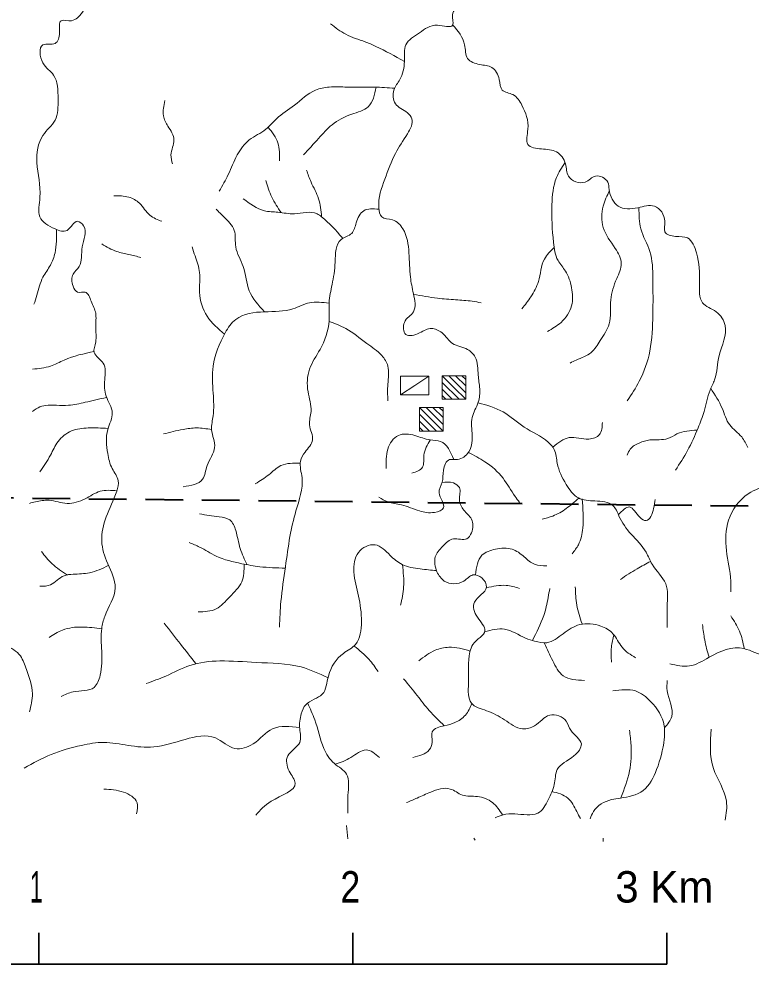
# Model space of a CAD drawing. Extents: x 788888 to 797112, y 8503144 to 8514989.
# Drawn here: x 791981 to 794313, y 8506322 to 8509330 of the extents above; entities that cross this region are included whole.
import ezdxf
from ezdxf.enums import TextEntityAlignment as Align

# ---------------------------------------------------------------- set-up
doc = ezdxf.new("R2010")
doc.units = 0
doc.header["$LTSCALE"] = 40
doc.linetypes.add('MEDIUM_DASHED', pattern=[4.5, 3, -1.5])
for name, color, linetype, lineweight in [('1', 7, 'Continuous', 13), ('15', 7, 'Continuous', 13), ('3', 7, 'Continuous', 13), ('60', 7, 'Continuous', 35), ('63', 7, 'MEDIUM_DASHED', 40)]:
    doc.layers.add(name, color=color, linetype=linetype, lineweight=lineweight)

msp = doc.modelspace()

# ---------------------------------------------------------------- linework, layer by layer
at = {"layer": '1'}
for p, q in [((793329.39, 8508194.65), (793367.39, 8508156.65)), ((793350.39, 8508194.65), (793404.39, 8508140.65)), ((793372.39, 8508194.65), (793404.39, 8508162.65)), ((793392.39, 8508194.65), (793404.39, 8508182.65)), ((793329.39, 8508173.65), (793383.39, 8508119.65)), ((793329.39, 8508151.65), (793361.39, 8508119.65)), ((793404.39, 8508119.65), (793367.39, 8508156.65)), ((793329.39, 8508131.65), (793341.39, 8508119.65)), ((793257.23, 8508093.43), (793295.23, 8508055.43)), ((793278.23, 8508093.43), (793332.23, 8508039.43)), ((793300.23, 8508093.43), (793332.23, 8508061.43)), ((793320.23, 8508093.43), (793332.23, 8508081.43)), ((793257.23, 8508072.43), (793311.23, 8508018.43)), ((793332.23, 8508018.43), (793295.23, 8508055.43)), ((793257.23, 8508050.43), (793289.23, 8508018.43)), ((793257.23, 8508030.43), (793269.23, 8508018.43))]:
    msp.add_line(p, q, dxfattribs=at)
for points in [[(793329.39, 8508194.65), (793329.39, 8508119.65), (793404.39, 8508119.65), (793404.39, 8508194.65)], [(793257.23, 8508093.43), (793257.23, 8508018.43), (793332.23, 8508018.43), (793332.23, 8508093.43)]]:
    msp.add_lwpolyline(points, close=True, dxfattribs=at)
at = {"layer": '15'}
for p, q in [((793025.16, 8506763.82), (793028.59, 8506721.2)), ((793434.68, 8506716.72), (793430.42, 8506723.11)), ((793841.86, 8506722.63), (793842.05, 8506712.23))]:
    msp.add_line(p, q, dxfattribs=at)
for points in [[(793382.88, 8509858.32), (793362.73, 8509818.94), (793367.53, 8509790.14), (793396.31, 8509766.15), (793410.69, 8509732.55), (793415.49, 8509684.55), (793449.06, 8509607.75), (793449.06, 8509545.35), (793420.29, 8509502.15), (793401.1, 8509473.35), (793401.1, 8509420.55), (793386.71, 8509377.36), (793362.73, 8509343.76), (793362.73, 8509310.16), (793314.77, 8509310.16), (793257.22, 8509286.16), (793214.05, 8509247.76), (793209.26, 8509194.96), (793194.87, 8509137.36), (793175.68, 8509103.76), (793180.48, 8509060.57), (793218.85, 8509031.77), (793233.24, 8509012.57), (793218.85, 8508964.57), (793180.48, 8508902.17), (793146.91, 8508820.57), (793127.72, 8508729.37), (793137.31, 8508700.58), (793170.89, 8508690.98), (793204.46, 8508662.18), (793223.65, 8508585.38), (793228.44, 8508508.58), (793238.03, 8508455.78), (793238.03, 8508398.18), (793209.26, 8508364.58), (793214.05, 8508326.19), (793257.22, 8508330.99), (793295.59, 8508345.39), (793329.16, 8508330.99), (793362.73, 8508297.39), (793410.69, 8508278.19), (793434.68, 8508254.19), (793444.27, 8508196.59), (793449.06, 8508153.39), (793444.27, 8508110.19), (793425.08, 8508062.19), (793425.08, 8508004.59), (793410.69, 8507947), (793372.33, 8507927.8), (793353.14, 8507927.8), (793333.96, 8507894.2), (793329.16, 8507855.8), (793319.57, 8507822.2), (793333.96, 8507774.2), (793305.18, 8507759.8), (793257.22, 8507764.6), (793199.66, 8507783.8), (793156.5, 8507793.4), (793127.72, 8507807.8)], [(792181.45, 8509443.12), (792152.67, 8509433.52), (792114.3, 8509471.92), (792075.93, 8509481.52), (792027.97, 8509481.52), (791999.19, 8509515.12), (791965.62, 8509539.12), (791932.05, 8509577.52), (791879.29, 8509572.72), (791845.72, 8509567.92), (791826.53, 8509534.32), (791807.35, 8509495.92), (791768.98, 8509491.12), (791725.82, 8509486.32), (791692.24, 8509457.52), (791687.45, 8509414.32), (791721.02, 8509351.92), (791730.61, 8509294.32), (791721.02, 8509275.13), (791663.47, 8509270.33), (791581.93, 8509294.32), (791514.79, 8509289.52), (791452.44, 8509260.73), (791423.66, 8509217.53), (791438.05, 8509179.13), (791466.82, 8509159.93), (791457.23, 8509126.33), (791394.88, 8509107.13), (791342.12, 8509073.53), (791313.35, 8509020.73), (791303.76, 8508982.33), (791265.39, 8508967.93), (791212.63, 8508967.93), (791183.85, 8508996.73), (791183.85, 8509049.53), (791193.44, 8509092.73), (791164.67, 8509164.73), (791121.5, 8509227.13), (791078.34, 8509275.13), (791059.15, 8509294.32), (791049.56, 8509327.92), (791020.78, 8509347.12), (790992.01, 8509356.72), (790943.08, 8509433.52), (790866.34, 8509495.92), (790813.58, 8509539.12), (790784.81, 8509553.52), (790746.44, 8509577.52), (790669.7, 8509567.92), (790616.94, 8509553.52), (790559.39, 8509577.52), (790444.28, 8509591.92), (790381.93, 8509577.52), (790324.38, 8509558.32), (790281.21, 8509543.92), (790170.9, 8509558.32), (790122.94, 8509591.92), (790055.79, 8509611.12), (789993.44, 8509611.12), (789950.28, 8509606.32), (789911.91, 8509563.12), (789887.93, 8509515.12), (789868.75, 8509481.52), (789830.38, 8509476.72), (789796.8, 8509491.12), (789772.82, 8509462.32), (789782.41, 8509423.92), (789796.8, 8509385.52), (789825.58, 8509390.32), (789835.17, 8509366.32), (789839.97, 8509270.33), (789796.8, 8509183.93), (789744.05, 8509126.33), (789720.07, 8509063.93), (789748.84, 8509044.73), (789763.23, 8509001.53), (789806.4, 8508977.53), (789839.97, 8508943.93), (789883.13, 8508915.14), (789897.52, 8508881.54), (789931.1, 8508867.14), (789974.26, 8508804.74), (790007.83, 8508723.14), (789988.65, 8508627.14), (789945.48, 8508526.35), (789907.11, 8508487.95), (789873.54, 8508454.35), (789825.58, 8508372.75), (789796.8, 8508305.55), (789734.45, 8508247.95), (789700.88, 8508199.96)], [(792181.45, 8509438.32), (792197.27, 8509396.56), (792168.5, 8509334.16), (792149.31, 8509324.56), (792115.74, 8509324.56), (792110.94, 8509286.16), (792096.55, 8509252.56), (792058.18, 8509247.76), (792058.18, 8509190.16), (792091.76, 8509151.76), (792106.15, 8509074.96), (792096.55, 8509007.77), (792058.18, 8508959.77), (792039, 8508873.37), (792048.59, 8508762.97), (792048.59, 8508700.58), (792096.55, 8508662.18), (792134.92, 8508657.38), (792168.5, 8508686.18), (792187.68, 8508671.78), (792182.88, 8508604.58), (792173.29, 8508542.18), (792154.11, 8508518.18), (792154.11, 8508479.78), (792168.5, 8508460.58), (792192.48, 8508460.58), (792211.66, 8508431.78), (792226.05, 8508393.38), (792226.05, 8508350.19), (792226.05, 8508302.19), (792221.25, 8508268.59), (792250.03, 8508234.99), (792254.83, 8508182.19), (792259.62, 8508129.39), (792278.81, 8508076.59), (792264.42, 8508023.79), (792264.42, 8507947), (792278.81, 8507899), (792297.99, 8507860.6), (792293.19, 8507827), (792259.62, 8507745.4), (792245.23, 8507668.6), (792264.42, 8507596.61), (792288.4, 8507519.81), (792254.83, 8507428.61), (792245.23, 8507390.21), (792245.23, 8507318.21), (792240.44, 8507241.42), (792221.25, 8507203.02), (792154.11, 8507188.62), (792115.74, 8507174.22)], [(793209.26, 8509194.96), (793118.13, 8509242.96), (793084.56, 8509257.36), (793022.21, 8509281.36), (792974.25, 8509314.96)], [(793363.59, 8509310.89), (793401.1, 8509247.76), (793410.69, 8509204.56), (793449.06, 8509185.36), (793487.43, 8509175.76), (793511.41, 8509137.36), (793521.01, 8509103.76), (793554.58, 8509089.36), (793583.36, 8509055.77), (793602.54, 8508978.97), (793602.54, 8508930.97), (793645.7, 8508916.57), (793693.67, 8508906.97), (793722.44, 8508868.57), (793732.04, 8508830.17), (793784.79, 8508810.97), (793818.37, 8508830.17), (793856.73, 8508810.97), (793861.53, 8508786.97), (793890.31, 8508734.17), (793952.66, 8508729.37), (794005.42, 8508734.17), (794038.99, 8508686.18), (794038.99, 8508652.58), (794072.56, 8508638.18), (794110.93, 8508633.38), (794139.71, 8508585.38), (794149.3, 8508489.38), (794158.89, 8508426.98), (794202.06, 8508398.18), (794230.83, 8508354.98), (794211.65, 8508258.99), (794197.26, 8508182.19), (794182.87, 8508148.59), (794163.69, 8508081.39), (794144.5, 8508028.59), (794110.93, 8507956.6), (794072.56, 8507894.2)], [(793178.49, 8509109.69), (793113.33, 8509113.36), (793027, 8509113.36), (792969.45, 8509113.36), (792926.28, 8509103.76), (792859.14, 8509055.77), (792801.59, 8509012.57), (792768.01, 8508978.97), (792715.25, 8508945.37), (792676.89, 8508897.37), (792648.11, 8508834.97), (792619.33, 8508782.17)], [(793119.02, 8509113.17), (793094.15, 8509050.97), (793041.39, 8509026.97), (792979.04, 8508993.37), (792935.88, 8508950.17), (792887.92, 8508897.37)], [(792446.67, 8509070.16), (792441.88, 8509022.17), (792456.26, 8508988.57), (792475.45, 8508945.37), (792465.86, 8508897.37), (792470.65, 8508868.57)], [(792775.21, 8508985.9), (792806.38, 8508935.77), (792811.18, 8508878.17)], [(793720.44, 8508872.42), (793693.67, 8508825.37), (793679.28, 8508738.97), (793684.07, 8508618.98), (793698.46, 8508561.38), (793722.44, 8508527.78), (793741.63, 8508474.98), (793741.63, 8508417.38), (793708.05, 8508364.58), (793664.89, 8508335.79)], [(792945.42, 8508700.64), (792935.88, 8508758.17), (792911.9, 8508810.97), (792897.51, 8508849.37)], [(792816.77, 8508713.99), (792787.2, 8508762.97), (792768.01, 8508815.77)], [(793862.54, 8508784.2), (793842.35, 8508734.17), (793842.35, 8508666.98), (793880.72, 8508599.78), (793899.9, 8508551.78), (793885.51, 8508503.78), (793866.33, 8508436.58), (793861.53, 8508359.78), (793832.75, 8508306.99), (793803.98, 8508268.59), (793756.02, 8508244.59), (793736.83, 8508234.99)], [(792283.6, 8508767.77), (792331.56, 8508762.97), (792365.14, 8508743.77), (792398.71, 8508705.38), (792437.08, 8508686.18)], [(793011.76, 8508633.55), (792945.47, 8508700.58), (792931.08, 8508710.17), (792859.14, 8508710.17), (792806.38, 8508714.97), (792763.22, 8508719.77), (792696.07, 8508758.17)], [(792763.22, 8508398.18), (792715.25, 8508465.38), (792696.07, 8508542.18), (792672.09, 8508604.58), (792667.29, 8508657.38), (792633.72, 8508700.58), (792609.74, 8508724.57)], [(793127.54, 8508724.77), (793079.76, 8508719.77), (793055.78, 8508681.38), (793041.39, 8508647.78), (793007.82, 8508628.58), (792988.63, 8508556.58), (792979.04, 8508484.58), (792969.45, 8508426.98), (792969.45, 8508369.38), (792940.67, 8508278.19), (792907.1, 8508215.79), (792902.3, 8508143.79), (792911.9, 8508081.39), (792907.1, 8508038.19), (792916.69, 8507990.2), (792892.71, 8507951.8), (792878.32, 8507923), (792883.12, 8507870.2), (792863.93, 8507764.6), (792844.75, 8507683), (792830.36, 8507587.01), (792815.97, 8507476.61), (792811.18, 8507395.01)], [(793956.3, 8508729.52), (793962.25, 8508662.18), (793991.03, 8508590.18), (794000.62, 8508503.78), (794000.62, 8508388.58), (793991.03, 8508273.39), (793957.45, 8508177.39), (793919.08, 8508114.99)], [(792101.03, 8508660.3), (792096.55, 8508585.38), (792082.16, 8508546.98), (792058.18, 8508508.58), (792039, 8508450.98), (792029.41, 8508422.18)], [(792245.23, 8508614.18), (792293.19, 8508590.18), (792331.56, 8508580.58), (792369.93, 8508570.98)], [(792636.49, 8508327.06), (792580.96, 8508383.78), (792556.98, 8508460.58), (792556.98, 8508522.98), (792542.59, 8508575.78), (792533, 8508604.58)], [(793686.44, 8508602.79), (793655.3, 8508566.18), (793636.11, 8508494.18), (793612.13, 8508446.18), (793583.36, 8508407.78)], [(793238.32, 8508453.8), (793314.77, 8508441.38), (793372.33, 8508436.58), (793425.08, 8508431.78), (793453.86, 8508426.98)], [(792969.21, 8508425.25), (792907.1, 8508426.98), (792854.34, 8508407.78), (792763.22, 8508398.18), (792672.09, 8508374.18), (792638.52, 8508330.99), (792600.15, 8508225.39), (792600.15, 8508138.99), (792600.15, 8508066.99), (792595.35, 8508023.79), (792604.94, 8507966.2), (792580.96, 8507908.6), (792566.57, 8507865.4), (792504.22, 8507841.4)], [(792969.19, 8508367.64), (793022.21, 8508345.39), (793089.35, 8508297.39), (793137.31, 8508258.99), (793156.5, 8508225.39), (793156.5, 8508167.79), (793156.5, 8508114.99)], [(795606.72, 8507971.64), (795537.46, 8508033.67), (795509.74, 8508103), (795447.38, 8508137.67), (795378.1, 8508158.47), (795322.67, 8508241.67), (795232.6, 8508262.48), (795163.31, 8508304.08), (795121.74, 8508297.14), (795080.16, 8508255.54), (795066.31, 8508200.07), (795017.81, 8508179.27), (794969.31, 8508172.34), (794969.31, 8508116.87), (794990.09, 8508061.4), (794955.45, 8508005.93), (794872.3, 8507992.06), (794823.8, 8507985.13), (794768.37, 8507936.59), (794657.52, 8507894.99), (794567.44, 8507846.46), (794484.3, 8507853.39), (794373.44, 8507846.46), (794304.15, 8507818.72), (794241.79, 8507735.52), (794234.87, 8507638.45), (794248.72, 8507541.38), (794248.72, 8507506.71)], [(792221.34, 8508272.04), (792125.33, 8508244.59), (792082.16, 8508225.39), (792024.61, 8508215.79)], [(794184.91, 8508153.95), (794221.24, 8508090.99), (794245.22, 8508038.19), (794283.59, 8507999.8), (794302.78, 8507966.2)], [(792260.16, 8508125.63), (792192.48, 8508110.19), (792139.72, 8508100.59), (792101.35, 8508100.59), (792048.59, 8508095.79), (792024.61, 8508081.39)], [(793443.94, 8508108.71), (793523.4, 8508079.42), (793590.55, 8508031.43), (793667.28, 8507983.43), (793686.47, 8507959.43), (793696.06, 8507916.23), (793724.84, 8507849.03), (793763.21, 8507805.83), (793815.96, 8507796.23), (793873.52, 8507781.83), (793892.7, 8507748.23), (793931.07, 8507690.64), (793979.03, 8507633.04), (793998.22, 8507594.64), (794041.38, 8507532.24), (794046.18, 8507460.24), (794046.18, 8507393.04)], [(792264.82, 8508026.98), (792202.07, 8508028.59), (792149.31, 8508018.99), (792106.15, 8507985.4), (792082.16, 8507942.2), (792048.59, 8507889.4)], [(792595.32, 8508023.31), (792547.39, 8508028.59), (792504.22, 8508023.79), (792441.88, 8508009.39)], [(793682.43, 8507967.26), (793734.43, 8507997.83), (793796.78, 8507993.03), (793830.35, 8508007.43), (793839.94, 8508045.83)], [(793366.6, 8507927.83), (793324.36, 8507985.4), (793290.79, 8507990.2), (793242.83, 8508004.59), (793190.07, 8508004.59), (793156.5, 8507961.4), (793151.7, 8507899)], [(794141.85, 8508021.99), (794077.36, 8508009.39), (794048.58, 8507995), (793991.03, 8507990.2), (793957.45, 8507980.6), (793928.68, 8507961.4), (793919.08, 8507942.2)], [(793291.72, 8507989.99), (793271.61, 8507942.2), (793266.81, 8507903.8), (793233.24, 8507884.6)], [(793413.22, 8507950.67), (793465.85, 8507921.03), (793523.4, 8507868.23), (793561.77, 8507810.63), (793576.16, 8507791.43)], [(792877.02, 8507916.63), (792815.97, 8507908.6), (792777.6, 8507879.8), (792734.44, 8507851)], [(793328.98, 8507854.91), (793365.13, 8507853.41), (793384.31, 8507839.01), (793384.31, 8507800.61), (793398.7, 8507767.01), (793422.68, 8507738.21), (793422.68, 8507695.01), (793408.29, 8507675.81), (793365.13, 8507675.81), (793331.55, 8507651.81), (793307.57, 8507618.22), (793312.37, 8507570.22)], [(792293.68, 8507828.46), (792240.44, 8507827), (792192.48, 8507803), (792134.92, 8507788.6), (792077.37, 8507798.2), (792034.2, 8507793.4), (792015.02, 8507788.6)], [(793764.61, 8507805.36), (793724.84, 8507772.23), (793681.67, 8507748.23), (793648.1, 8507738.63)], [(793775.15, 8507802.58), (793777.59, 8507709.84), (793763.21, 8507657.04), (793744.02, 8507628.24)], [(793890.57, 8507751.94), (793926.27, 8507777.03), (793959.85, 8507743.43), (793979.03, 8507733.83), (794003.01, 8507772.23), (794007.81, 8507801.03)], [(792708.71, 8507592.93), (792686.48, 8507644.61), (792672.09, 8507702.2), (792652.91, 8507735.8), (792619.33, 8507745.4), (792556.98, 8507755)], [(792136.23, 8507560.4), (792086.96, 8507596.61), (792053.39, 8507635.01)], [(792829.69, 8507582.3), (792748.83, 8507587.01), (792691.27, 8507596.61), (792609.74, 8507620.61), (792556.98, 8507649.4), (792523.41, 8507663.8)], [(793311.94, 8507574.49), (793259.61, 8507579.82), (793202.06, 8507594.22), (793163.69, 8507623.02), (793115.73, 8507656.61), (793062.97, 8507632.62), (793048.58, 8507570.22), (793062.97, 8507493.42), (793072.56, 8507411.82), (793053.38, 8507339.82), (793015.01, 8507311.02), (792967.05, 8507239.03), (792947.86, 8507181.43), (792895.11, 8507147.83), (792880.72, 8507119.03), (792875.92, 8507071.03), (792875.92, 8507027.83), (792837.55, 8506984.63), (792842.35, 8506936.63), (792861.53, 8506898.24), (792784.79, 8506840.64), (792736.05, 8506796.5)], [(793435.85, 8507560.7), (793456.25, 8507623.44), (793499.42, 8507642.64), (793552.18, 8507642.64), (793590.55, 8507618.64), (793624.12, 8507594.64), (793662.49, 8507589.84)], [(792266.23, 8507590.64), (792206.86, 8507567.81), (792154.11, 8507563.01), (792125.33, 8507558.21), (792082.16, 8507529.41), (792048.59, 8507524.61)], [(792698.79, 8507595.02), (792691.27, 8507539.01), (792652.91, 8507491.01), (792609.74, 8507452.61), (792552.19, 8507443.01)], [(793202.79, 8507593.78), (793206.85, 8507522.22), (793197.26, 8507464.62)], [(793993.57, 8507603.92), (793950.26, 8507580.24), (793897.5, 8507546.64)], [(793312.37, 8507570.22), (793336.35, 8507541.42), (793398.7, 8507541.42), (793427.48, 8507560.62), (793456.25, 8507551.02), (793470.64, 8507522.22), (793432.27, 8507474.22), (793441.86, 8507426.22), (793465.85, 8507383.02), (793427.48, 8507339.82), (793417.88, 8507315.82), (793413.09, 8507215.03), (793422.68, 8507152.63), (793470.64, 8507128.63), (793528.2, 8507099.83), (793585.75, 8507071.03), (793624.12, 8507080.63), (793672.08, 8507114.23), (793724.84, 8507095.03), (793739.23, 8507066.23), (793772.8, 8507023.03), (793748.82, 8506984.63), (793696.06, 8506941.43), (793686.47, 8506893.44), (793667.28, 8506845.44), (793633.71, 8506802.24), (793600.14, 8506797.44), (793523.4, 8506797.44), (793498.33, 8506788.09)], [(793470.44, 8507519.6), (793532.99, 8507527.44), (793576.16, 8507517.84)], [(793616.97, 8507352.09), (793652.89, 8507431.44), (793667.28, 8507489.04), (793672.08, 8507517.84)], [(793774.95, 8507405.63), (793758.41, 8507465.04), (793753.61, 8507522.64)], [(794291.58, 8507326.57), (794276.44, 8507381.9), (794248.72, 8507430.44)], [(792245.12, 8507389.01), (792182.88, 8507395.01), (792120.53, 8507385.41), (792077.37, 8507361.41)], [(792544.68, 8507278.57), (792497.03, 8507339.82), (792444.27, 8507407.02)], [(793465, 8507379.4), (793528.2, 8507388.24), (793595.34, 8507359.44), (793624.12, 8507349.85), (793662.49, 8507345.05), (793715.24, 8507373.84), (793768, 8507402.64), (793835.15, 8507397.84), (793873.52, 8507373.84), (793902.29, 8507330.65), (793945.46, 8507297.05)], [(794179.43, 8507298.7), (794165.58, 8507354.17), (794158.65, 8507402.7)], [(793876.49, 8507370.52), (793868.72, 8507330.65), (793868.72, 8507282.65)], [(791694.25, 8507292.74), (791784.8, 8507322.06), (791842.36, 8507336.46), (791880.72, 8507346.06), (791938.28, 8507336.46), (791986.24, 8507302.86), (792005.42, 8507259.66), (792024.61, 8507182.86), (792015.02, 8507125.26)], [(793049.06, 8507334.43), (793096.54, 8507291.82), (793125.32, 8507253.43)], [(793655.92, 8507342.89), (793681.67, 8507287.45), (793715.24, 8507239.45), (793782.39, 8507225.05)], [(794538.91, 8507263.37), (794484.3, 8507326.43), (794442.73, 8507333.37), (794359.58, 8507305.63), (794290.3, 8507326.43), (794179.44, 8507298.7), (794117.08, 8507270.96), (794054.72, 8507277.9)], [(793418.46, 8507318.53), (793350.74, 8507330.65), (793307.57, 8507321.05), (793254.82, 8507287.45)], [(792964.59, 8507233.95), (792880.72, 8507267.83), (792736.83, 8507282.23), (792621.73, 8507287.02), (792525.8, 8507272.63), (792449.06, 8507239.03), (792386.72, 8507215.03)], [(793336.35, 8507081.05), (793288.39, 8507129.05), (793250.02, 8507177.05), (793206.85, 8507229.85)], [(794037.7, 8507074.51), (794060.57, 8507109.85), (794046.18, 8507191.45), (794046.18, 8507225.05)], [(793801.08, 8506784.75), (793811.17, 8506807.46), (793868.72, 8506845.86), (793897.5, 8506850.66), (793969.44, 8506874.66), (794012.61, 8506941.86), (794036.59, 8507037.85), (794036.59, 8507081.05), (793993.42, 8507157.85), (793945.46, 8507191.45), (793873.52, 8507191.45)], [(792900.22, 8507153.21), (792923.88, 8507099.83), (792952.66, 8507008.63), (792986.23, 8506960.63), (793024.6, 8506927.04), (793029.4, 8506859.84), (793029.4, 8506802.24)], [(793424.49, 8507151.72), (793403.5, 8507114.65), (793369.92, 8507090.65), (793336.35, 8507081.05), (793297.98, 8507061.85), (793297.98, 8507028.25), (793288.39, 8507004.25), (793235.63, 8506980.26)], [(792876.17, 8507074.86), (792789.59, 8507071.03), (792727.24, 8507023.03), (792669.69, 8507008.63), (792607.34, 8507042.23), (792511.41, 8507037.43), (792410.7, 8507013.43), (792329.16, 8507018.23), (792252.42, 8507027.83), (792180.48, 8507018.23), (792084.56, 8506989.43), (791998.23, 8506946.23)], [(793898.55, 8506850.91), (793926.27, 8506937.06), (793931.07, 8507018.65), (793926.27, 8507066.65)], [(794231.11, 8506780.01), (794234.87, 8506841.08), (794193.29, 8506945.08), (794186.37, 8507069.89)], [(792988.5, 8506958.13), (793038.99, 8506979.83), (793086.95, 8507003.83), (793130.12, 8506979.83)], [(793521.75, 8506797.12), (793489.83, 8506836.26), (793441.86, 8506855.46), (793393.9, 8506860.26), (793355.53, 8506879.46), (793293.18, 8506869.86), (793250.02, 8506850.66), (793216.45, 8506836.26)], [(792356.43, 8506800.69), (792357.94, 8506835.84), (792314.77, 8506869.44), (792252.42, 8506879.04)], [(793678.68, 8506871.76), (793729.63, 8506850.66), (793758.41, 8506807.46), (793769.92, 8506785.1)]]:
    msp.add_spline(points, degree=3, dxfattribs=at)
at = {"layer": '3'}
for p in [(793287.1, 8508193.74), (793197.1, 8508133.74)]:
    msp.add_line(p, (793242.1, 8508163.74), dxfattribs=at)
msp.add_lwpolyline([(793197.1, 8508133.74), (793287.1, 8508133.74), (793287.1, 8508193.74), (793197.1, 8508193.74)], close=True, dxfattribs=at)
at = {"layer": '60'}
for p, q in [((792045.22, 8506322.26), (792045.22, 8506422.26)), ((793045.22, 8506322.26), (793045.22, 8506422.26)), ((794045.22, 8506322.26), (794045.22, 8506422.26)), ((791045.22, 8506322.26), (794045.22, 8506322.26))]:
    msp.add_line(p, q, dxfattribs=at)
at = {"layer": '63'}
msp.add_lwpolyline([(795985.61, 8513296.58), (795924.11, 8507761.4), (790507.28, 8507821.14), (790567.65, 8513356.12), (795985.61, 8513296.58)], close=True, dxfattribs=at)

# ---------------------------------------------------------------- texts
at = {"layer": '60'}
for s, width, p in [('1', 0.55, (792037.07, 8506518.1)), ('2', 0.85, (793037.07, 8506518.1))]:
    msp.add_text(s, height=100, dxfattribs=dict(at, width=width)).set_placement(p, align=Align.CENTER)
msp.add_text('3 Km', height=100, dxfattribs=at).set_placement((794037.07, 8506518.1), align=Align.CENTER)

doc.saveas('drawing.dxf')
